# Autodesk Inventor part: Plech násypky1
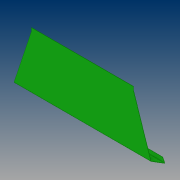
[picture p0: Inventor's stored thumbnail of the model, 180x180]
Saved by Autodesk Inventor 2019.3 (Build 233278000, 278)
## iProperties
Created: 2019-02
Part Number: Plech násypky1
Material: Ocel, měkká, svařovaná
Document SubType Name: Plech
Designer: B-hon
Density: 7.85 g/cm^3
Sheet Metal Rule: Výchozí_mm
Appearance: Tmavě zelená
Author: B-hon
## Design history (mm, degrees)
node "Plocha1"
  sketch "Náčrt1"
    geometry: L1 (354, 12.5)-(-354, 12.5); L2 (-354, 12.5)-(-354, -12.5); L3 (354, -12.5)-(354, 12.5); L4 (354, 12.5)-(-354, -12.5); L5 (-354, 12.5)-(354, -12.5); L6 (354, -12.5)-(474.727, -377.075); L7 (474.727, -377.075)-(-474.727, -377.075); L8 (-474.727, -377.075)-(-354, -12.5); 1 further point
    constraints: 16 end point, 2 horizontal, 2 midpoint, 1 parallel, 1 perpendicular
    dimensions: "d0" = 708 distance of L3.start L2.end; "d1" = 25 distance of L3.start L1.start; "d26" = 389.575 distance between parallel lines of L7 L1; "d27" = 18.322 deg angle of L2 L8; "d28" = 18.322 deg angle of L6 L3 (= d27)
node "Obruba2"
node "Obruba3"
sketch "Náčrt6"
  geometry: L1 (910.259, 16.195)-(977.698, -51.244); L2 (977.698, -51.244)-(976.481, 55.634); L3 (976.481, 55.634)-(910.259, 16.195); L4 (97.271, 74.271)-(-102.437, -125.437); L5 (-102.437, -125.437)-(-125.534, 95.903); L6 (-125.534, 95.903)-(97.271, 74.271); L7 (0, 0)-(949.454, 0) reference; L8 (0, 0)-(0, -23); L9 (949.454, -20.06)-(949.454, 0) reference; L10 (949.454, 0)-(949.454, -23); 1 further point
  constraints: 16 end point, 2 point on line, 1 collinear, 1 vertical
  dimensions: "d46" = 23 distance of L7.start L8.end; "d47" = 23 distance of L7.end L10.end; "d48" = 45 deg angle of L9 L1; "d49" = 45 deg angle of L4 L8
extrude "Vysunutí1" cut sketch "Náčrt6" distance "d50" = 2; taper "d51" = 0 deg
sketch "Náčrt7"
  geometry: L1 (354, 12.5)-(-354, 12.5) reference; L2 (354, 12.5)-(363.149, 12.5); L3 (363.149, 12.5)-(363.149, -14); L4 (363.149, -14)-(354, -14); L5 (354, -14)-(354, 12.5); L6 (-354, 12.5)-(-366.874, 12.5); L7 (-366.874, 12.5)-(-366.874, -14); L8 (-366.874, -14)-(-354, -14); L9 (-354, -14)-(-354, 12.5); 1 further point
  constraints: 16 end point, 4 parallel, 2 horizontal, 2 perpendicular
  dimensions: "d52" = 26.5 distance of L2.end L3.end; "d53" = 26.5 distance of L7.end L6.end
extrude "Vysunutí2" cut sketch "Náčrt7" distance "d54" = 10; taper "d55" = 0 deg
node "Těleso1"
feature "Deska1" dims "d5" = 2 (= Tloušťka)
sketch "Náčrt3"
  geometry: L1 through (474.727, 0) direction (-1, 0); L2 through (0, -57.5) direction (0, -1); L3 (0, -115)-(949.454, -115); L4 (949.454, -115)-(949.454, 0)
  constraints: 6 end point, 1 horizontal, 1 perpendicular, 1 vertical
feature "Deska3" dims "d5" = 2 (= Tloušťka), "d16" = 2 (= ŠířkaVýštipu), "d17" = 1 (= HloubkaVýštipu), "d18" = 4 (= MinimálníZbytek), "d19" = 2 (= PřechodovýPoloměr), "d20" = 115, "d21" = 58 deg, "d22" = 2 (= PoloměrOhybu), "d23" = 8 (= VelikostRohovéhoVýštipu), "d24" = 2 (= VelikostMezery), "d25" = 2 (= VelikostJacobihoPoloměru), "MezeraVystřižení" = 0.01
feature "Ohyb2" dims "d5" = 2 (= Tloušťka), "d16" = 2 (= ŠířkaVýštipu), "d17" = 1 (= HloubkaVýštipu), "d18" = 4 (= MinimálníZbytek), "d19" = 2 (= PřechodovýPoloměr), "d20" = 115, "d21" = 58 deg, "d22" = 2 (= PoloměrOhybu), "MezeraVystřižení" = 0.01
feature "Roh2" dims "d20" = 115, "d21" = 58 deg, "d23" = 8 (= VelikostRohovéhoVýštipu), "d24" = 2 (= VelikostMezery), "d25" = 2 (= VelikostJacobihoPoloměru)
sketch "Náčrt5"
  geometry: L1 through (474.727, 0) direction (-1, -5.05e-19); L2 through (0, -12.5) direction (5.05e-19, -1); L3 (0, -25)-(949.454, -25); L4 (949.454, -25)-(949.454, 0)
  constraints: 6 end point, 1 horizontal, 1 perpendicular, 1 vertical
feature "Deska4" dims "d5" = 2 (= Tloušťka), "d30" = 2 (= ŠířkaVýštipu), "d31" = 1 (= HloubkaVýštipu), "d32" = 4 (= MinimálníZbytek), "d33" = 2 (= PřechodovýPoloměr), "d34" = 25, "d35" = 102 deg, "d36" = 2 (= PoloměrOhybu), "d37" = 8 (= VelikostRohovéhoVýštipu), "d38" = 2 (= VelikostMezery), "d39" = 2 (= VelikostJacobihoPoloměru), "MezeraVystřižení" = 0.01
feature "Ohyb3" dims "d5" = 2 (= Tloušťka), "d30" = 2 (= ŠířkaVýštipu), "d31" = 1 (= HloubkaVýštipu), "d32" = 4 (= MinimálníZbytek), "d33" = 2 (= PřechodovýPoloměr), "d34" = 25, "d35" = 102 deg, "d36" = 2 (= PoloměrOhybu), "MezeraVystřižení" = 0.01
feature "Roh3" dims "d34" = 25, "d35" = 102 deg, "d37" = 8 (= VelikostRohovéhoVýštipu), "d38" = 2 (= VelikostMezery), "d39" = 2 (= VelikostJacobihoPoloměru)
other parameters: "Tloušťka" = 2 (derived), "KSoučinitel" = 4.4, "PoloměrOhybu" = 2 (= Tloušťka), "ŠířkaVýštipu" = 2 (= Tloušťka), "HloubkaVýštipu" = 1 (= 0.5 x Tloušťka), "VelikostRohovéhoVýštipu" = 8 (= 4 x Tloušťka), "MinimálníZbytek" = 4 (= 2 x Tloušťka), "PřechodovýPoloměr" = 2 (= PoloměrOhybu), "VelikostJacobihoPoloměru" = 2 (= PoloměrOhybu), "VelikostMezery" = 2 (= Tloušťka)
